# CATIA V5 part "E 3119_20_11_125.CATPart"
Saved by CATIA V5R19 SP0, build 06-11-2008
Nomenclature: E 3119_20_11_125
Description: PART-E 3119_20_11_125-DESC
Property "Hersteller": "Meusburger"
Property "Material": "2.0598 180 HB / Graphit _ graphite"
Property "Bestellnummer": "E 3119/20/11/125"
Property "Teilenummer": "E 3119/20/11/125"
Property "Beschreibung": "Führungsleiste einseitig, wartungsfrei, mit Schraubenbohrungen _ One-sided self lubricating guiding rail, with screw holes"
Material "Brass": density 8216 kg/m3, Young's modulus 1.31e+11 Pa, Poisson ratio 0.35, thermal expansion 1.67e-05 1/K
Bounding box of the stored display mesh (mm): x 0 to 125, y -5 to 15, z 0 to 20
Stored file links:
  G:\UTB\Kombinované\Bakalářská práce\Catia\FORMA\E 3119_20_11_125.CATPart
  D:\Aplikace\CATIA\Nová složka\win_b64\startup\materials\Catalog.CATMaterial
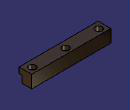
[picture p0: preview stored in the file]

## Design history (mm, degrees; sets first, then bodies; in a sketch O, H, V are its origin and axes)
Body1 "E 3119_20_11_125" (main body)
  Solid1: solid without history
